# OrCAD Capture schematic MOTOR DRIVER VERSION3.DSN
size A
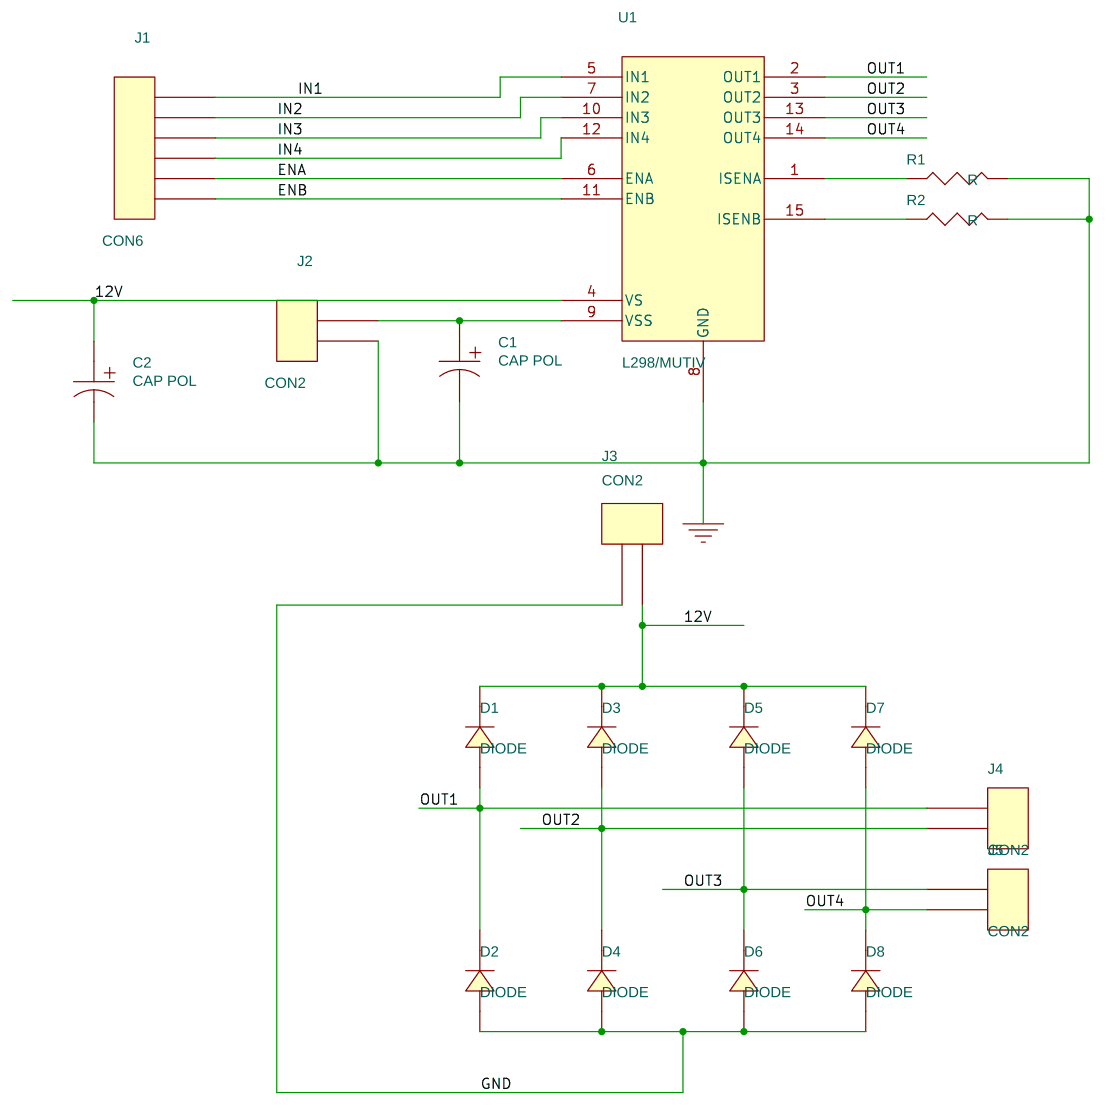
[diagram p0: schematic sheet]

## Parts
C1  CAP POL  [gu-CAPCYL200]
C2  CAP POL  [gu-CAPCYL200]
D1  DIODE  [gu-1N4001]
D2  DIODE  [gu-1N4001]
D3  DIODE  [gu-1N4001]
D4  DIODE  [gu-1N4001]
D5  DIODE  [gu-1N4001]
D6  DIODE  [gu-1N4001]
D7  DIODE  [gu-1N4001]
D8  DIODE  [gu-1N4001]
J1  CON6  [gu-molex6]
J2  CON2  [gu-molex2]
J3  CON2  [gu-molex2]
J4  CON2  [gu-molex2]
J5  CON2  [gu-molex2]
R1  R  [gu-RC400]
R2  R  [gu-RC400]
U1  L298/MUTIV  [GU-L298-HSINK2]

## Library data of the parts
C1 C2 = CAP_POL
D1-D8 = DIODE
J1 = CON6
J2-J5 = CON2
R1 R2 = R
U1 = L298_MUTIV_0

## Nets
12V: C2.1 D1.1(K) D3.1(K) D5.1(K) D7.1(K) J3.2 U1.4(VS)
GND: C1.2 C2.2 D2.2(A) D4.2(A) D6.2(A) D8.2(A) J2.2 J3.1 R1.2 R2.2 U1.8(GND)
ENA: J1.5 U1.6(ENA)
ENB: J1.6 U1.11(ENB)
IN1: J1.1 U1.5(IN1)
IN2: J1.2 U1.7(IN2)
IN3: J1.3 U1.10(IN3)
IN4: J1.4 U1.12(IN4)
OUT1: D1.2(A) D2.1(K) J4.1 U1.2(OUT1)
OUT2: D3.2(A) D4.1(K) J4.2 U1.3(OUT2)
OUT3: D5.2(A) D6.1(K) J5.1 U1.13(OUT3)
OUT4: D7.2(A) D8.1(K) J5.2 U1.14(OUT4)
N00290: C1.1 J2.1 U1.9(VSS)
N00456: R1.1 U1.1(ISENA)
N00460: R2.1 U1.15(ISENB)
